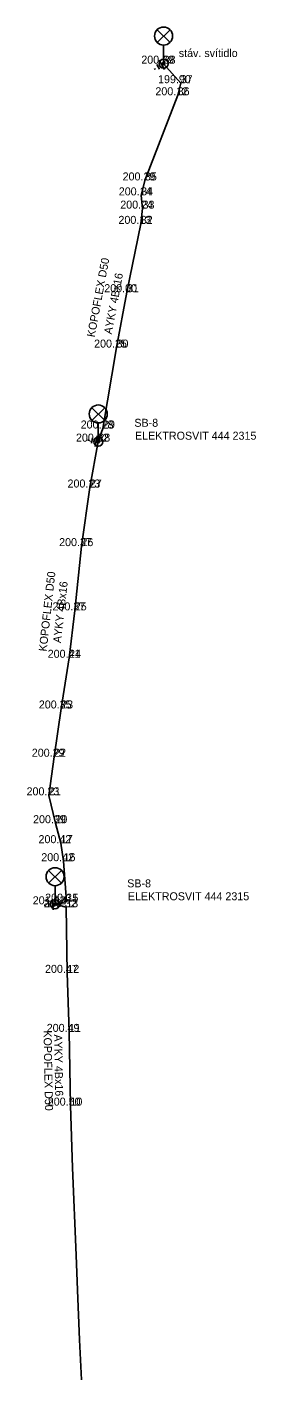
# Model space of a CAD drawing. Extents: x -539674 to -539600, y -1156466 to -1156081.
# Drawn here: x -539621.6 to -539600.1, y -1156465.7 to -1156338.9 of the extents above; entities that cross this region are included whole.
import ezdxf

# ---------------------------------------------------------------- set-up
doc = ezdxf.new("R2010")
doc.units = 0
for name, color, linetype in [('Vrstva 1', 7, 'Continuous'), ('Vrstva 10', 7, 'Continuous'), ('Vrstva 16', 7, 'Continuous'), ('Vrstva 2', 7, 'Continuous'), ('Vrstva 20', 7, 'Continuous'), ('Vrstva 22', 7, 'Continuous'), ('Vrstva 3', 7, 'Continuous'), ('Vrstva 35', 7, 'Continuous')]:
    doc.layers.add(name, color=color, linetype=linetype)

msp = doc.modelspace()

# ---------------------------------------------------------------- linework, layer by layer
at = {"layer": 'Vrstva 1'}
for p, q in [((-539608.8, -1156342.34), (-539608.8, -1156342.34)), ((-539607.2, -1156344.17), (-539607.2, -1156344.17)), ((-539607.48, -1156345.3), (-539607.48, -1156345.3)), ((-539610.55, -1156353.28), (-539610.55, -1156353.28)), ((-539610.91, -1156354.68), (-539610.91, -1156354.68)), ((-539610.77, -1156355.92), (-539610.77, -1156355.92)), ((-539610.94, -1156357.35), (-539610.94, -1156357.35)), ((-539612.24, -1156363.75), (-539612.24, -1156363.75)), ((-539613.21, -1156368.94), (-539613.21, -1156368.94)), ((-539614.48, -1156376.52), (-539614.48, -1156376.52)), ((-539614.92, -1156377.75), (-539614.92, -1156377.75)), ((-539615.71, -1156382.05), (-539615.71, -1156382.05)), ((-539616.5, -1156387.54), (-539616.5, -1156387.54)), ((-539617.12, -1156393.56), (-539617.12, -1156393.56)), ((-539617.66, -1156398), (-539617.66, -1156398)), ((-539618.4, -1156402.75), (-539618.4, -1156402.75)), ((-539619.06, -1156407.27), (-539619.06, -1156407.27)), ((-539619.55, -1156410.89), (-539619.55, -1156410.89)), ((-539618.94, -1156413.5), (-539618.94, -1156413.5)), ((-539618.43, -1156415.37), (-539618.43, -1156415.37)), ((-539618.17, -1156417.06), (-539618.17, -1156417.06)), ((-539618.97, -1156421.1), (-539618.97, -1156421.1)), ((-539617.92, -1156421.37), (-539617.92, -1156421.37)), ((-539617.9, -1156420.85), (-539617.9, -1156420.85)), ((-539617.82, -1156427.52), (-539617.82, -1156427.52)), ((-539617.66, -1156433.05), (-539617.66, -1156433.05)), ((-539617.53, -1156439.96), (-539617.53, -1156439.96))]:
    msp.add_line(p, q, dxfattribs=at)
at = {"layer": 'Vrstva 10'}
for p, q in [((-539609.4, -1156339.16), (-539608.2, -1156340.35)), ((-539609.4, -1156340.35), (-539608.2, -1156339.16)), ((-539608.8, -1156342.34), (-539608.8, -1156340.6)), ((-539609.23, -1156342.01), (-539608.72, -1156342.87)), ((-539609.64, -1156342.8), (-539609.58, -1156342.89)), ((-539609.45, -1156342.43), (-539609.19, -1156342.86)), ((-539608.97, -1156342.44), (-539608.8, -1156342.34)), ((-539615.52, -1156374.57), (-539614.32, -1156375.76)), ((-539615.52, -1156375.76), (-539614.32, -1156374.57)), ((-539614.92, -1156377.75), (-539614.92, -1156376.01)), ((-539615.85, -1156377.55), (-539615.87, -1156377.66)), ((-539615.47, -1156377.4), (-539615.56, -1156377.89)), ((-539615.03, -1156377.22), (-539615.21, -1156378.21)), ((-539615.12, -1156377.71), (-539614.92, -1156377.75)), ((-539619.57, -1156417.92), (-539618.38, -1156419.11)), ((-539619.57, -1156419.11), (-539618.38, -1156417.92)), ((-539618.97, -1156421.1), (-539618.97, -1156419.36)), ((-539619.2, -1156420.61), (-539619.15, -1156421.61)), ((-539619.92, -1156421.12), (-539619.92, -1156421.23)), ((-539619.58, -1156420.88), (-539619.56, -1156421.38)), ((-539619.17, -1156421.11), (-539618.97, -1156421.1))]:
    msp.add_line(p, q, dxfattribs=at)
for centre, radius in [((-539608.8, -1156339.75), 0.844), ((-539608.8, -1156342.34), 0.427), ((-539608.8, -1156342.34), 0.113), ((-539614.92, -1156375.16), 0.844), ((-539614.92, -1156377.75), 0.427), ((-539614.92, -1156377.75), 0.113), ((-539618.97, -1156418.51), 0.844), ((-539618.97, -1156421.1), 0.427), ((-539618.97, -1156421.1), 0.113)]:
    msp.add_circle(centre, radius, dxfattribs=at)
at = {"layer": 'Vrstva 22'}
msp.add_lwpolyline([(-539608.8, -1156342.34), (-539607.2, -1156344.17), (-539607.48, -1156345.3), (-539610.55, -1156353.28), (-539610.91, -1156354.68), (-539610.77, -1156355.92), (-539610.94, -1156357.35), (-539612.24, -1156363.75), (-539613.21, -1156368.94), (-539614.48, -1156376.52), (-539614.92, -1156377.75), (-539615.71, -1156382.05), (-539616.5, -1156387.54), (-539617.12, -1156393.56), (-539617.66, -1156398), (-539618.4, -1156402.75), (-539619.06, -1156407.27), (-539619.55, -1156410.89), (-539618.94, -1156413.5), (-539618.43, -1156415.37), (-539618.17, -1156417.06), (-539617.9, -1156420.85), (-539618.97, -1156421.1), (-539617.92, -1156421.37), (-539617.82, -1156427.52), (-539617.66, -1156433.05), (-539617.53, -1156439.96), (-539617.33, -1156445.78), (-539617, -1156453.98), (-539616.87, -1156457.25), (-539616.68, -1156461.91), (-539616.48, -1156465.66)], dxfattribs=at)
at = {"layer": 'Vrstva 35'}
msp.add_lwpolyline([(-539608.8, -1156342.34), (-539607.2, -1156344.17), (-539607.48, -1156345.3), (-539610.55, -1156353.28), (-539610.91, -1156354.68), (-539610.77, -1156355.92), (-539610.94, -1156357.35), (-539612.24, -1156363.75), (-539613.21, -1156368.94), (-539614.48, -1156376.52), (-539614.92, -1156377.75), (-539615.71, -1156382.05), (-539616.5, -1156387.54), (-539617.12, -1156393.56), (-539617.66, -1156398), (-539618.4, -1156402.75), (-539619.06, -1156407.27), (-539619.55, -1156410.89), (-539618.94, -1156413.5), (-539618.43, -1156415.37), (-539618.17, -1156417.06), (-539617.9, -1156420.85), (-539618.97, -1156421.1), (-539617.92, -1156421.37), (-539617.82, -1156427.52), (-539617.66, -1156433.05), (-539617.53, -1156439.96), (-539617.33, -1156445.78), (-539617, -1156453.98), (-539616.87, -1156457.25), (-539616.68, -1156461.91), (-539616.48, -1156465.66)], dxfattribs=at)

# ---------------------------------------------------------------- texts
at = {"layer": 'Vrstva 16'}
for s, p in [('stáv. svítidlo', (-539607.38, -1156341.72)), ('SB-8', (-539611.54, -1156376.36)), ('ELEKTROSVIT 444 2315', (-539611.48, -1156377.57)), ('SB-8', (-539612.21, -1156419.51)), ('ELEKTROSVIT 444 2315', (-539612.15, -1156420.72))]:
    msp.add_text(s, height=0.75, dxfattribs=at).set_placement(p)
for rotation, p in [(79.411, (-539613.66, -1156367.73)), (83.67, (-539618.42, -1156396.65)), (271.0776, (-539619.06, -1156433.29))]:
    msp.add_text('AYKY 4Bx16', height=0.75, rotation=rotation, dxfattribs=at).set_placement(p)
at = {"layer": 'Vrstva 2'}
for s, p in [('38', (-539608.8, -1156342.34)), ('36', (-539607.48, -1156345.3)), ('37', (-539607.2, -1156344.17)), ('35', (-539610.55, -1156353.28)), ('34', (-539610.91, -1156354.68)), ('33', (-539610.77, -1156355.92)), ('32', (-539610.94, -1156357.35)), ('31', (-539612.24, -1156363.75)), ('30', (-539613.21, -1156368.94)), ('29', (-539614.48, -1156376.52)), ('28', (-539614.92, -1156377.75)), ('27', (-539615.71, -1156382.05)), ('26', (-539616.5, -1156387.54)), ('25', (-539617.12, -1156393.56)), ('24', (-539617.66, -1156398)), ('23', (-539618.4, -1156402.75)), ('22', (-539619.06, -1156407.27)), ('21', (-539619.55, -1156410.89)), ('20', (-539618.94, -1156413.5)), ('17', (-539618.43, -1156415.37)), ('16', (-539618.17, -1156417.06)), ('14', (-539618.97, -1156421.1)), ('13', (-539617.92, -1156421.37)), ('15', (-539617.9, -1156420.85)), ('12', (-539617.82, -1156427.52)), ('11', (-539617.66, -1156433.05)), ('10', (-539617.53, -1156439.96))]:
    msp.add_text(s, height=0.75, dxfattribs=at).set_placement(p)
at = {"layer": 'Vrstva 20'}
for rotation, p in [(79.411, (-539615.26, -1156368.01)), (83.67, (-539619.76, -1156397.44)), (271.0776, (-539620.05, -1156432.92))]:
    msp.add_text('KOPOFLEX D50', height=0.75, rotation=rotation, dxfattribs=at).set_placement(p)
at = {"layer": 'Vrstva 3'}
for s, p in [('200.79', (-539610.89, -1156342.34)), ('200.12', (-539609.57, -1156345.3)), ('199.90', (-539609.32, -1156344.17)), ('200.29', (-539612.64, -1156353.28)), ('200.14', (-539613, -1156354.68)), ('200.24', (-539612.86, -1156355.92)), ('200.13', (-539613.03, -1156357.35)), ('200.00', (-539614.36, -1156363.75)), ('200.25', (-539615.31, -1156368.94)), ('200.28', (-539616.57, -1156376.52)), ('200.92', (-539617.01, -1156377.75)), ('200.23', (-539617.8, -1156382.05)), ('200.37', (-539618.59, -1156387.54)), ('200.37', (-539619.21, -1156393.56)), ('200.41', (-539619.66, -1156398)), ('200.35', (-539620.49, -1156402.75)), ('200.29', (-539621.15, -1156407.27)), ('200.23', (-539621.64, -1156410.89)), ('200.39', (-539621.03, -1156413.5)), ('200.42', (-539620.52, -1156415.37)), ('200.42', (-539620.26, -1156417.06)), ('201.02', (-539621.06, -1156421.1)), ('200.32', (-539620.01, -1156421.37)), ('200.31', (-539619.9, -1156420.85)), ('200.47', (-539619.91, -1156427.52)), ('200.49', (-539619.75, -1156433.05)), ('200.50', (-539619.65, -1156439.96))]:
    msp.add_text(s, height=0.75, dxfattribs=at).set_placement(p)

doc.saveas('drawing.dxf')
